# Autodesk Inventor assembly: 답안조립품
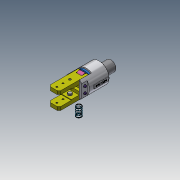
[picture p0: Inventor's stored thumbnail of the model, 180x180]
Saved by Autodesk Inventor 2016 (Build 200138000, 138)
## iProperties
Created: 2019-02
Part Number: 답안조립품
Material: 일반
Document SubType Name: Assembly
Designer: Administrator
Author: Administrator
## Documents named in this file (11)
- C:\Users\Administrator\Desktop\490207V1022\답안조립품.iam
- C:\Users\Administrator\Desktop\490207V1022\본체.ipt
- C:\Users\Administrator\Desktop\490207V1022\E-링.ipt
- C:\Users\Administrator\Desktop\490207V1022\O-링.ipt
- C:\Users\Administrator\Desktop\490207V1022\가이드핀.ipt
- C:\Users\Administrator\Desktop\490207V1022\부시.ipt
- C:\Users\Administrator\Desktop\490207V1022\스프링.ipt
- C:\Users\Administrator\Desktop\490207V1022\평행핀 6x28.ipt
- C:\Users\Administrator\Desktop\490207V1022\피스톤.ipt
- C:\Users\Administrator\Desktop\490207V1022\핀.ipt
- C:\Users\Administrator\Desktop\490207V1022\핑거.ipt
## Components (13 placed, 6 different names)
1. E-링:1
2. O-링:1
3. 가이드핀:1
4. 피스톤:1 — 각도:1
5. 핀:1
6. 핑거:1 — 각도:2
7. O-링:2
8. 핑거:2 — 각도:3
9. 핀:2
10. 가이드핀:2
11. E-링:2
12. E-링:3
13. E-링:4
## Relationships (3: Angle 3)
- 각도:1 [Angle]: 피스톤:1
- 각도:2 [Angle]: 핑거:1
- 각도:3 [Angle]: 핑거:2
